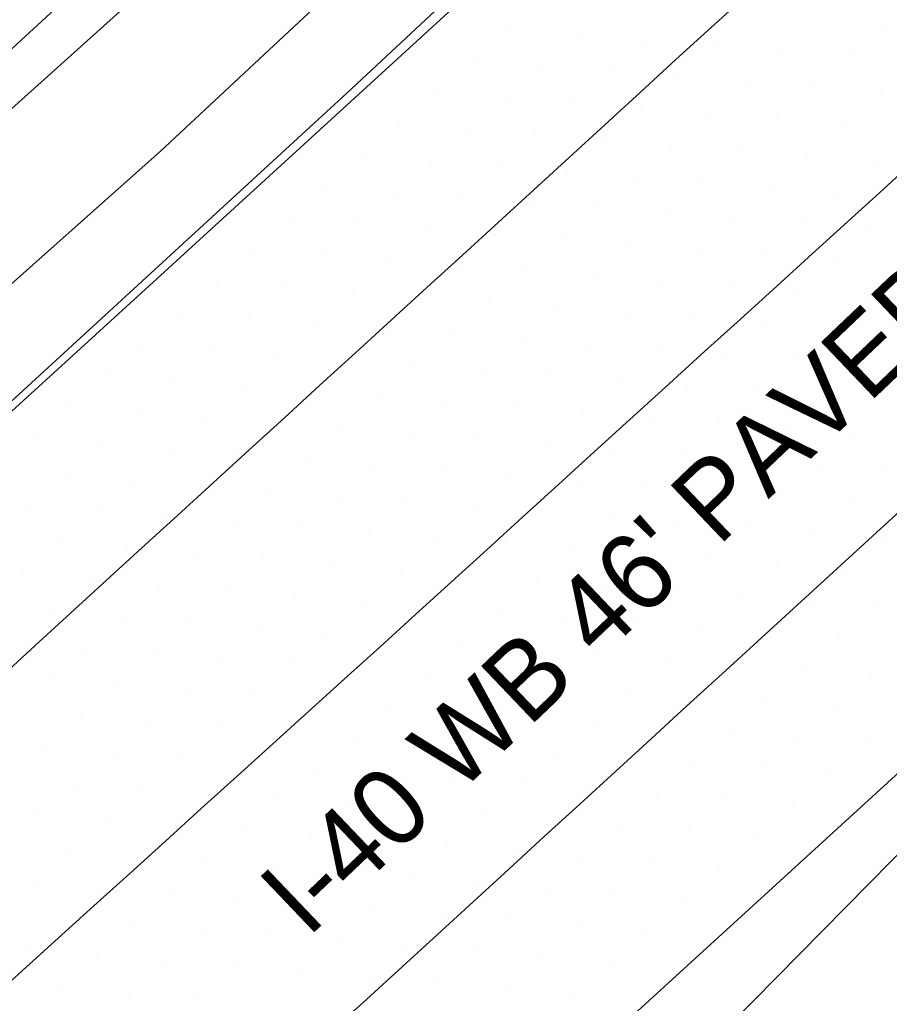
# Model space of a CAD drawing. Extents: x 1548934 to 1561348, y 809680 to 824075.
# Drawn here: x 1551931.4 to 1551976.5, y 810879.7 to 810930.7 of the extents above; entities that cross this region are included whole.
import ezdxf

# ---------------------------------------------------------------- set-up
doc = ezdxf.new("R2010")
doc.units = 0
for name, color, linetype in [('E_NCDOT_Vertical_Profile_Ground_Line', 7, 'Continuous'), ('Exist DTM Scan Elevation Point', 7, 'Continuous'), ('Exist Guardrail', 7, 'Continuous'), ('Exist Roads EOP Text', 7, 'Continuous'), ('P_RDY_Terminator_Cell', 7, 'Continuous'), ('PH Exist DTM Breakline', 7, 'Continuous')]:
    doc.layers.add(name, color=color, linetype=linetype)

msp = doc.modelspace()

# ---------------------------------------------------------------- linework, layer by layer
at = {"layer": 'E_NCDOT_Vertical_Profile_Ground_Line'}
for points in [[(1551916.371, 810897.058), (1551938.535, 810917.275), (1551960.652, 810937.518), (1551982.56, 810958.014), (1552004.504, 810978.339), (1552026.319, 810998.917), (1552048.088, 811019.511), (1552069.812, 811040.132), (1552091.656, 811060.693), (1552113.491, 811081.331), (1552135.259, 811101.951), (1552157.034, 811122.672), (1552170.309, 811135.33)], [(1551914.384, 810835.022), (1551936.744, 810855.141), (1551959.052, 810875.312), (1551981.204, 810895.541), (1552003.401, 810915.836), (1552025.394, 810936.238), (1552047.401, 810956.625), (1552069.375, 810977.048), (1552091.258, 810997.731), (1552113.074, 811018.285), (1552134.788, 811038.984), (1552156.584, 811059.597), (1552178.385, 811080.204), (1552200.189, 811100.809)]]:
    msp.add_lwpolyline(points, dxfattribs=at)
at = {"layer": 'Exist DTM Scan Elevation Point'}
for p, q in [((1551956.8, 810930.162), (1551956.8, 810930.162)), ((1551976.321, 810930.451), (1551976.321, 810930.451)), ((1551960.325, 810929.894), (1551960.325, 810929.894)), ((1551963.849, 810929.626), (1551963.849, 810929.626)), ((1551967.374, 810929.358), (1551967.374, 810929.358)), ((1551970.9, 810929.09), (1551970.9, 810929.09)), ((1551974.425, 810928.822), (1551974.425, 810928.822)), ((1551954.903, 810928.532), (1551954.903, 810928.532)), ((1551958.428, 810928.265), (1551958.428, 810928.265)), ((1551961.953, 810927.997), (1551961.953, 810927.997)), ((1551965.478, 810927.729), (1551965.478, 810927.729)), ((1551969.003, 810927.461), (1551969.003, 810927.461)), ((1551972.528, 810927.194), (1551972.528, 810927.194)), ((1551953.007, 810926.904), (1551953.007, 810926.904)), ((1551956.532, 810926.636), (1551956.532, 810926.636)), ((1551976.054, 810926.926), (1551976.054, 810926.926)), ((1551960.057, 810926.368), (1551960.057, 810926.368)), ((1551963.582, 810926.1), (1551963.582, 810926.1)), ((1551967.107, 810925.832), (1551967.107, 810925.832)), ((1551970.632, 810925.565), (1551970.632, 810925.565)), ((1551951.111, 810925.275), (1551951.111, 810925.275)), ((1551974.157, 810925.297), (1551974.157, 810925.297)), ((1551954.636, 810925.007), (1551954.636, 810925.007)), ((1551958.16, 810924.739), (1551958.16, 810924.739)), ((1551961.685, 810924.471), (1551961.685, 810924.471)), ((1551965.211, 810924.203), (1551965.211, 810924.203)), ((1551949.214, 810923.646), (1551949.214, 810923.646)), ((1551968.736, 810923.936), (1551968.736, 810923.936)), ((1551972.261, 810923.668), (1551972.261, 810923.668)), ((1551952.739, 810923.378), (1551952.739, 810923.378)), ((1551956.264, 810923.11), (1551956.264, 810923.11)), ((1551975.786, 810923.4), (1551975.786, 810923.4)), ((1551959.789, 810922.842), (1551959.789, 810922.842)), ((1551963.314, 810922.575), (1551963.314, 810922.575)), ((1551947.318, 810922.017), (1551947.318, 810922.017)), ((1551966.839, 810922.307), (1551966.839, 810922.307)), ((1551970.365, 810922.039), (1551970.365, 810922.039)), ((1551950.843, 810921.749), (1551950.843, 810921.749)), ((1551954.368, 810921.481), (1551954.368, 810921.481)), ((1551973.89, 810921.772), (1551973.89, 810921.772)), ((1551957.893, 810921.213), (1551957.893, 810921.213)), ((1551961.418, 810920.946), (1551961.418, 810920.946)), ((1551964.943, 810920.678), (1551964.943, 810920.678)), ((1551945.422, 810920.388), (1551945.422, 810920.388)), ((1551948.946, 810920.12), (1551948.946, 810920.12)), ((1551968.468, 810920.41), (1551968.468, 810920.41)), ((1551971.993, 810920.143), (1551971.993, 810920.143)), ((1551952.471, 810919.852), (1551952.471, 810919.852)), ((1551955.996, 810919.584), (1551955.996, 810919.584)), ((1551975.518, 810919.875), (1551975.518, 810919.875)), ((1551959.521, 810919.317), (1551959.521, 810919.317)), ((1551963.046, 810919.049), (1551963.046, 810919.049)), ((1551943.526, 810918.759), (1551943.526, 810918.759)), ((1551947.05, 810918.491), (1551947.05, 810918.491)), ((1551966.572, 810918.781), (1551966.572, 810918.781)), ((1551970.097, 810918.514), (1551970.097, 810918.514)), ((1551950.575, 810918.223), (1551950.575, 810918.223)), ((1551954.1, 810917.955), (1551954.1, 810917.955)), ((1551973.622, 810918.246), (1551973.622, 810918.246)), ((1551957.625, 810917.688), (1551957.625, 810917.688)), ((1551961.15, 810917.42), (1551961.15, 810917.42)), ((1551941.629, 810917.13), (1551941.629, 810917.13)), ((1551964.675, 810917.152), (1551964.675, 810917.152)), ((1551945.154, 810916.862), (1551945.154, 810916.862)), ((1551948.679, 810916.595), (1551948.679, 810916.595)), ((1551968.201, 810916.885), (1551968.201, 810916.885)), ((1551971.726, 810916.617), (1551971.726, 810916.617)), ((1551952.203, 810916.326), (1551952.203, 810916.326)), ((1551955.729, 810916.059), (1551955.729, 810916.059)), ((1551975.251, 810916.349), (1551975.251, 810916.349)), ((1551939.733, 810915.501), (1551939.733, 810915.501)), ((1551959.254, 810915.791), (1551959.254, 810915.791)), ((1551962.779, 810915.523), (1551962.779, 810915.523)), ((1551943.257, 810915.233), (1551943.257, 810915.233)), ((1551946.782, 810914.966), (1551946.782, 810914.966)), ((1551966.304, 810915.256), (1551966.304, 810915.256)), ((1551969.829, 810914.988), (1551969.829, 810914.988)), ((1551950.307, 810914.698), (1551950.307, 810914.698)), ((1551953.832, 810914.43), (1551953.832, 810914.43)), ((1551973.354, 810914.72), (1551973.354, 810914.72)), ((1551937.836, 810913.873), (1551937.836, 810913.873)), ((1551957.357, 810914.162), (1551957.357, 810914.162)), ((1551960.883, 810913.895), (1551960.883, 810913.895)), ((1551941.361, 810913.605), (1551941.361, 810913.605)), ((1551944.886, 810913.337), (1551944.886, 810913.337)), ((1551964.408, 810913.627), (1551964.408, 810913.627)), ((1551967.933, 810913.359), (1551967.933, 810913.359)), ((1551948.411, 810913.069), (1551948.411, 810913.069)), ((1551971.458, 810913.091), (1551971.458, 810913.091)), ((1551974.983, 810912.824), (1551974.983, 810912.824)), ((1551951.936, 810912.801), (1551951.936, 810912.801)), ((1551955.461, 810912.533), (1551955.461, 810912.533)), ((1551935.94, 810912.243), (1551935.94, 810912.243)), ((1551939.465, 810911.976), (1551939.465, 810911.976)), ((1551958.986, 810912.266), (1551958.986, 810912.266)), ((1551962.511, 810911.998), (1551962.511, 810911.998)), ((1551942.99, 810911.708), (1551942.99, 810911.708)), ((1551946.514, 810911.44), (1551946.514, 810911.44)), ((1551966.036, 810911.73), (1551966.036, 810911.73)), ((1551969.562, 810911.463), (1551969.562, 810911.463)), ((1551950.04, 810911.172), (1551950.04, 810911.172)), ((1551953.565, 810910.904), (1551953.565, 810910.904)), ((1551973.087, 810911.195), (1551973.087, 810911.195)), ((1551934.043, 810910.615), (1551934.043, 810910.615)), ((1551937.568, 810910.346), (1551937.568, 810910.346)), ((1551957.09, 810910.637), (1551957.09, 810910.637)), ((1551960.615, 810910.369), (1551960.615, 810910.369)), ((1551941.093, 810910.079), (1551941.093, 810910.079)), ((1551944.618, 810909.811), (1551944.618, 810909.811)), ((1551964.14, 810910.101), (1551964.14, 810910.101)), ((1551967.665, 810909.834), (1551967.665, 810909.834)), ((1551948.143, 810909.543), (1551948.143, 810909.543)), ((1551951.668, 810909.275), (1551951.668, 810909.275)), ((1551971.19, 810909.566), (1551971.19, 810909.566)), ((1551974.715, 810909.298), (1551974.715, 810909.298)), ((1551932.147, 810908.985), (1551932.147, 810908.985)), ((1551955.194, 810909.008), (1551955.194, 810909.008)), ((1551958.719, 810908.74), (1551958.719, 810908.74)), ((1551935.672, 810908.718), (1551935.672, 810908.718)), ((1551939.197, 810908.45), (1551939.197, 810908.45)), ((1551962.244, 810908.472), (1551962.244, 810908.472)), ((1551942.722, 810908.182), (1551942.722, 810908.182)), ((1551946.247, 810907.914), (1551946.247, 810907.914)), ((1551965.769, 810908.205), (1551965.769, 810908.205)), ((1551969.294, 810907.937), (1551969.294, 810907.937)), ((1551949.772, 810907.646), (1551949.772, 810907.646)), ((1551953.297, 810907.379), (1551953.297, 810907.379)), ((1551972.819, 810907.669), (1551972.819, 810907.669)), ((1551976.344, 810907.402), (1551976.344, 810907.402)), ((1551933.775, 810907.089), (1551933.775, 810907.089)), ((1551937.3, 810906.821), (1551937.3, 810906.821)), ((1551956.822, 810907.111), (1551956.822, 810907.111)), ((1551960.347, 810906.843), (1551960.347, 810906.843)), ((1551940.825, 810906.553), (1551940.825, 810906.553)), ((1551944.35, 810906.285), (1551944.35, 810906.285)), ((1551963.872, 810906.576), (1551963.872, 810906.576)), ((1551967.398, 810906.308), (1551967.398, 810906.308)), ((1551947.876, 810906.018), (1551947.876, 810906.018)), ((1551951.401, 810905.75), (1551951.401, 810905.75)), ((1551970.923, 810906.04), (1551970.923, 810906.04)), ((1551974.448, 810905.773), (1551974.448, 810905.773)), ((1551931.879, 810905.46), (1551931.879, 810905.46)), ((1551935.404, 810905.192), (1551935.404, 810905.192)), ((1551954.926, 810905.482), (1551954.926, 810905.482)), ((1551958.451, 810905.215), (1551958.451, 810905.215)), ((1551938.929, 810904.924), (1551938.929, 810904.924)), ((1551942.454, 810904.656), (1551942.454, 810904.656)), ((1551961.976, 810904.947), (1551961.976, 810904.947)), ((1551965.501, 810904.679), (1551965.501, 810904.679)), ((1551945.979, 810904.389), (1551945.979, 810904.389)), ((1551969.026, 810904.411), (1551969.026, 810904.411)), ((1551972.552, 810904.144), (1551972.552, 810904.144)), ((1551949.504, 810904.121), (1551949.504, 810904.121)), ((1551953.03, 810903.853), (1551953.03, 810903.853)), ((1551976.077, 810903.877), (1551976.077, 810903.877)), ((1551933.507, 810903.563), (1551933.507, 810903.563)), ((1551937.033, 810903.295), (1551937.033, 810903.295)), ((1551956.555, 810903.586), (1551956.555, 810903.586)), ((1551960.08, 810903.318), (1551960.08, 810903.318)), ((1551940.558, 810903.027), (1551940.558, 810903.027)), ((1551944.083, 810902.76), (1551944.083, 810902.76)), ((1551963.605, 810903.05), (1551963.605, 810903.05)), ((1551967.13, 810902.782), (1551967.13, 810902.782)), ((1551947.608, 810902.492), (1551947.608, 810902.492)), ((1551951.133, 810902.224), (1551951.133, 810902.224)), ((1551970.655, 810902.515), (1551970.655, 810902.515)), ((1551974.181, 810902.248), (1551974.181, 810902.248)), ((1551931.611, 810901.934), (1551931.611, 810901.934)), ((1551935.136, 810901.666), (1551935.136, 810901.666)), ((1551954.658, 810901.957), (1551954.658, 810901.957)), ((1551958.183, 810901.689), (1551958.183, 810901.689)), ((1551938.661, 810901.398), (1551938.661, 810901.398)), ((1551942.186, 810901.131), (1551942.186, 810901.131)), ((1551961.708, 810901.421), (1551961.708, 810901.421)), ((1551965.233, 810901.154), (1551965.233, 810901.154)), ((1551945.712, 810900.863), (1551945.712, 810900.863)), ((1551949.237, 810900.596), (1551949.237, 810900.596)), ((1551968.759, 810900.886), (1551968.759, 810900.886)), ((1551972.284, 810900.619), (1551972.284, 810900.619)), ((1551952.762, 810900.328), (1551952.762, 810900.328)), ((1551975.81, 810900.352), (1551975.81, 810900.352)), ((1551933.24, 810900.037), (1551933.24, 810900.037)), ((1551936.765, 810899.769), (1551936.765, 810899.769)), ((1551956.287, 810900.06), (1551956.287, 810900.06)), ((1551959.812, 810899.792), (1551959.812, 810899.792)), ((1551940.29, 810899.502), (1551940.29, 810899.502)), ((1551943.815, 810899.234), (1551943.815, 810899.234)), ((1551963.337, 810899.524), (1551963.337, 810899.524)), ((1551966.862, 810899.257), (1551966.862, 810899.257)), ((1551947.34, 810898.967), (1551947.34, 810898.967)), ((1551950.866, 810898.699), (1551950.866, 810898.699)), ((1551970.388, 810898.99), (1551970.388, 810898.99)), ((1551973.914, 810898.723), (1551973.914, 810898.723)), ((1551934.868, 810898.141), (1551934.868, 810898.141)), ((1551954.391, 810898.431), (1551954.391, 810898.431)), ((1551957.916, 810898.163), (1551957.916, 810898.163)), ((1551938.394, 810897.873), (1551938.394, 810897.873)), ((1551941.919, 810897.605), (1551941.919, 810897.605)), ((1551961.441, 810897.896), (1551961.441, 810897.896)), ((1551964.966, 810897.628), (1551964.966, 810897.628)), ((1551945.444, 810897.338), (1551945.444, 810897.338)), ((1551948.969, 810897.07), (1551948.969, 810897.07)), ((1551968.491, 810897.361), (1551968.491, 810897.361)), ((1551972.017, 810897.094), (1551972.017, 810897.094)), ((1551932.972, 810896.512), (1551932.972, 810896.512)), ((1551952.494, 810896.802), (1551952.494, 810896.802)), ((1551956.019, 810896.534), (1551956.019, 810896.534)), ((1551975.543, 810896.827), (1551975.543, 810896.827)), ((1551936.497, 810896.244), (1551936.497, 810896.244)), ((1551959.544, 810896.267), (1551959.544, 810896.267)), ((1551963.07, 810895.999), (1551963.07, 810895.999)), ((1551940.022, 810895.976), (1551940.022, 810895.976)), ((1551943.548, 810895.709), (1551943.548, 810895.709)), ((1551966.595, 810895.732), (1551966.595, 810895.732)), ((1551947.073, 810895.441), (1551947.073, 810895.441)), ((1551950.598, 810895.173), (1551950.598, 810895.173)), ((1551970.121, 810895.465), (1551970.121, 810895.465)), ((1551973.647, 810895.198), (1551973.647, 810895.198)), ((1551934.601, 810894.615), (1551934.601, 810894.615)), ((1551954.123, 810894.906), (1551954.123, 810894.906)), ((1551957.648, 810894.638), (1551957.648, 810894.638)), ((1551938.126, 810894.347), (1551938.126, 810894.347)), ((1551941.651, 810894.08), (1551941.651, 810894.08)), ((1551961.173, 810894.37), (1551961.173, 810894.37)), ((1551964.699, 810894.103), (1551964.699, 810894.103)), ((1551945.176, 810893.812), (1551945.176, 810893.812)), ((1551948.701, 810893.544), (1551948.701, 810893.544)), ((1551968.224, 810893.836), (1551968.224, 810893.836)), ((1551971.75, 810893.569), (1551971.75, 810893.569)), ((1551932.704, 810892.986), (1551932.704, 810892.986)), ((1551952.227, 810893.277), (1551952.227, 810893.277)), ((1551955.752, 810893.009), (1551955.752, 810893.009)), ((1551975.276, 810893.302), (1551975.276, 810893.302)), ((1551936.23, 810892.718), (1551936.23, 810892.718)), ((1551939.755, 810892.451), (1551939.755, 810892.451)), ((1551959.277, 810892.741), (1551959.277, 810892.741)), ((1551962.802, 810892.474), (1551962.802, 810892.474)), ((1551943.28, 810892.183), (1551943.28, 810892.183)), ((1551946.805, 810891.915), (1551946.805, 810891.915)), ((1551966.328, 810892.207), (1551966.328, 810892.207)), ((1551969.854, 810891.94), (1551969.854, 810891.94)), ((1551950.33, 810891.648), (1551950.33, 810891.648)), ((1551973.38, 810891.673), (1551973.38, 810891.673)), ((1551934.333, 810891.089), (1551934.333, 810891.089)), ((1551953.855, 810891.38), (1551953.855, 810891.38)), ((1551957.38, 810891.112), (1551957.38, 810891.112)), ((1551937.859, 810890.822), (1551937.859, 810890.822)), ((1551941.384, 810890.554), (1551941.384, 810890.554)), ((1551960.906, 810890.845), (1551960.906, 810890.845)), ((1551964.432, 810890.578), (1551964.432, 810890.578)), ((1551944.909, 810890.287), (1551944.909, 810890.287)), ((1551948.434, 810890.019), (1551948.434, 810890.019)), ((1551967.958, 810890.311), (1551967.958, 810890.311)), ((1551971.484, 810890.044), (1551971.484, 810890.044)), ((1551932.437, 810889.461), (1551932.437, 810889.461)), ((1551951.959, 810889.751), (1551951.959, 810889.751)), ((1551955.484, 810889.484), (1551955.484, 810889.484)), ((1551935.962, 810889.193), (1551935.962, 810889.193)), ((1551939.487, 810888.925), (1551939.487, 810888.925)), ((1551959.009, 810889.216), (1551959.009, 810889.216)), ((1551962.535, 810888.949), (1551962.535, 810888.949)), ((1551943.012, 810888.658), (1551943.012, 810888.658)), ((1551946.537, 810888.39), (1551946.537, 810888.39)), ((1551966.061, 810888.682), (1551966.061, 810888.682)), ((1551969.587, 810888.415), (1551969.587, 810888.415)), ((1551950.063, 810888.122), (1551950.063, 810888.122)), ((1551953.588, 810887.855), (1551953.588, 810887.855)), ((1551934.066, 810887.564), (1551934.066, 810887.564)), ((1551957.113, 810887.587), (1551957.113, 810887.587)), ((1551960.639, 810887.32), (1551960.639, 810887.32)), ((1551937.591, 810887.296), (1551937.591, 810887.296)), ((1551941.116, 810887.029), (1551941.116, 810887.029)), ((1551964.165, 810887.053), (1551964.165, 810887.053)), ((1551944.641, 810886.761), (1551944.641, 810886.761)), ((1551948.166, 810886.493), (1551948.166, 810886.493)), ((1551967.691, 810886.786), (1551967.691, 810886.786)), ((1551932.169, 810885.935), (1551932.169, 810885.935)), ((1551951.691, 810886.226), (1551951.691, 810886.226)), ((1551955.217, 810885.958), (1551955.217, 810885.958)), ((1551935.695, 810885.667), (1551935.695, 810885.667)), ((1551939.22, 810885.4), (1551939.22, 810885.4)), ((1551958.743, 810885.691), (1551958.743, 810885.691)), ((1551962.268, 810885.424), (1551962.268, 810885.424)), ((1551942.745, 810885.132), (1551942.745, 810885.132)), ((1551946.27, 810884.864), (1551946.27, 810884.864)), ((1551965.794, 810885.157), (1551965.794, 810885.157)), ((1551949.795, 810884.597), (1551949.795, 810884.597)), ((1551953.32, 810884.329), (1551953.32, 810884.329)), ((1551933.798, 810884.039), (1551933.798, 810884.039)), ((1551937.323, 810883.771), (1551937.323, 810883.771)), ((1551956.846, 810884.062), (1551956.846, 810884.062)), ((1551960.372, 810883.795), (1551960.372, 810883.795)), ((1551940.848, 810883.503), (1551940.848, 810883.503)), ((1551963.898, 810883.528), (1551963.898, 810883.528)), ((1551944.373, 810883.235), (1551944.373, 810883.235)), ((1551947.899, 810882.968), (1551947.899, 810882.968)), ((1551931.902, 810882.41), (1551931.902, 810882.41)), ((1551951.424, 810882.7), (1551951.424, 810882.7)), ((1551954.95, 810882.433), (1551954.95, 810882.433)), ((1551935.427, 810882.142), (1551935.427, 810882.142)), ((1551938.952, 810881.874), (1551938.952, 810881.874)), ((1551958.476, 810882.166), (1551958.476, 810882.166)), ((1551962.002, 810881.899), (1551962.002, 810881.899)), ((1551942.477, 810881.607), (1551942.477, 810881.607)), ((1551946.002, 810881.339), (1551946.002, 810881.339)), ((1551949.528, 810881.071), (1551949.528, 810881.071)), ((1551953.053, 810880.804), (1551953.053, 810880.804)), ((1551933.53, 810880.513), (1551933.53, 810880.513)), ((1551937.056, 810880.245), (1551937.056, 810880.245)), ((1551956.579, 810880.537), (1551956.579, 810880.537)), ((1551960.105, 810880.27), (1551960.105, 810880.27)), ((1551940.581, 810879.978), (1551940.581, 810879.978))]:
    msp.add_line(p, q, dxfattribs=at)
at = {"layer": 'Exist Guardrail'}
msp.add_lwpolyline([(1551757.983, 810757.324), (1551769.38, 810767.068), (1551780.686, 810776.926), (1551791.953, 810786.827), (1551803.251, 810796.694), (1551814.514, 810806.594), (1551825.811, 810816.461), (1551837.07, 810826.37), (1551848.296, 810836.318), (1551859.509, 810846.279), (1551870.676, 810856.292), (1551881.798, 810866.357), (1551892.982, 810876.353), (1551904.137, 810886.38), (1551915.273, 810896.429), (1551926.283, 810906.614), (1551937.333, 810916.757), (1551948.379, 810926.903), (1551959.351, 810937.132), (1551970.296, 810947.379), (1551981.198, 810957.682), (1551992.011, 810968.086), (1552001.046, 810976.727), (1552002.786, 810977.64)], dxfattribs=at)
at = {"layer": 'P_RDY_Terminator_Cell'}
for points in [[(1551930.375, 810896.583), (1551932.221, 810898.269), (1551934.066, 810899.955), (1551935.912, 810901.641), (1551937.758, 810903.328), (1551939.603, 810905.014), (1551941.449, 810906.7), (1551943.295, 810908.387), (1551945.14, 810910.073), (1551946.986, 810911.759), (1551948.832, 810913.445), (1551950.677, 810915.132), (1551952.523, 810916.818), (1551954.369, 810918.504), (1551956.214, 810920.191), (1551958.059, 810921.878), (1551959.902, 810923.567), (1551961.745, 810925.256), (1551963.588, 810926.946), (1551965.431, 810928.635), (1551967.273, 810930.324), (1551969.116, 810932.014)], [(1551977.845, 810923.436), (1551975.995, 810921.754), (1551974.145, 810920.073), (1551972.296, 810918.391), (1551970.446, 810916.709), (1551968.596, 810915.028), (1551966.746, 810913.346), (1551964.896, 810911.664), (1551963.046, 810909.983), (1551961.196, 810908.301), (1551959.346, 810906.62), (1551957.496, 810904.938), (1551955.647, 810903.256), (1551953.797, 810901.575), (1551951.947, 810899.893), (1551950.097, 810898.211), (1551948.245, 810896.532), (1551946.392, 810894.853), (1551944.539, 810893.175), (1551942.687, 810891.497), (1551940.834, 810889.818), (1551938.981, 810888.14), (1551937.128, 810886.462), (1551935.275, 810884.784), (1551933.422, 810883.105), (1551931.569, 810881.427), (1551929.716, 810879.749)], [(1551977.049, 810905.251), (1551975.205, 810903.563), (1551973.361, 810901.874), (1551971.517, 810900.186), (1551969.674, 810898.498), (1551967.83, 810896.809), (1551965.986, 810895.121), (1551964.142, 810893.433), (1551962.299, 810891.744), (1551960.455, 810890.056), (1551958.611, 810888.368), (1551956.767, 810886.679), (1551954.924, 810884.991), (1551953.08, 810883.303), (1551951.236, 810881.614), (1551949.392, 810879.926), (1551947.536, 810878.251)]]:
    msp.add_lwpolyline(points, dxfattribs=at)
at = {"layer": 'PH Exist DTM Breakline'}
for points in [[(1551976.063, 810969.117), (1551949.262, 810946.008), (1551929.742, 810928.027), (1551906.224, 810905.666), (1551886.676, 810885.568), (1551862.451, 810861.533), (1551842.48, 810843.549), (1551829.474, 810833.372), (1551817.96, 810825.212), (1551812.063, 810821.762), (1551801.327, 810815.073)], [(1551976.365, 810967.374), (1551948.686, 810941.996), (1551929.965, 810925.173), (1551906.224, 810905.666)], [(1551840.823, 810836.732), (1551856.549, 810850.401), (1551870.567, 810863.56), (1551885.818, 810877.518), (1551900.338, 810889.87), (1551921.207, 810908.312), (1551938.697, 810923.865), (1551967.629, 810950.867), (1551980.751, 810963.343)], [(1551970.464, 810846.555), (1551960.001, 810834.752), (1551951.548, 810826.961), (1551947.606, 810824.705), (1551945.944, 810824.438), (1551944.64, 810824.717), (1551942.953, 810825.408), (1551939.935, 810827.336), (1551937.901, 810828.513), (1551936.138, 810829.602), (1551934.552, 810831.054), (1551933.909, 810832.404), (1551933.112, 810834.731), (1551932.73, 810837.259), (1551932.763, 810839.809), (1551933.185, 810841.223), (1551937.926, 810847.5), (1551946.735, 810856.017), (1551954.732, 810864.256), (1551967.029, 810877.412), (1551979.009, 810889.553), (1552001.605, 810910.226)]]:
    msp.add_lwpolyline(points, dxfattribs=at)

# ---------------------------------------------------------------- texts
at = {"layer": 'Exist Roads EOP Text'}
msp.add_text("I-40 WB 46' PAVED", height=4.02, rotation=43.6313, dxfattribs=at).set_placement((1551946.334, 810883.071))

doc.saveas('drawing.dxf')
